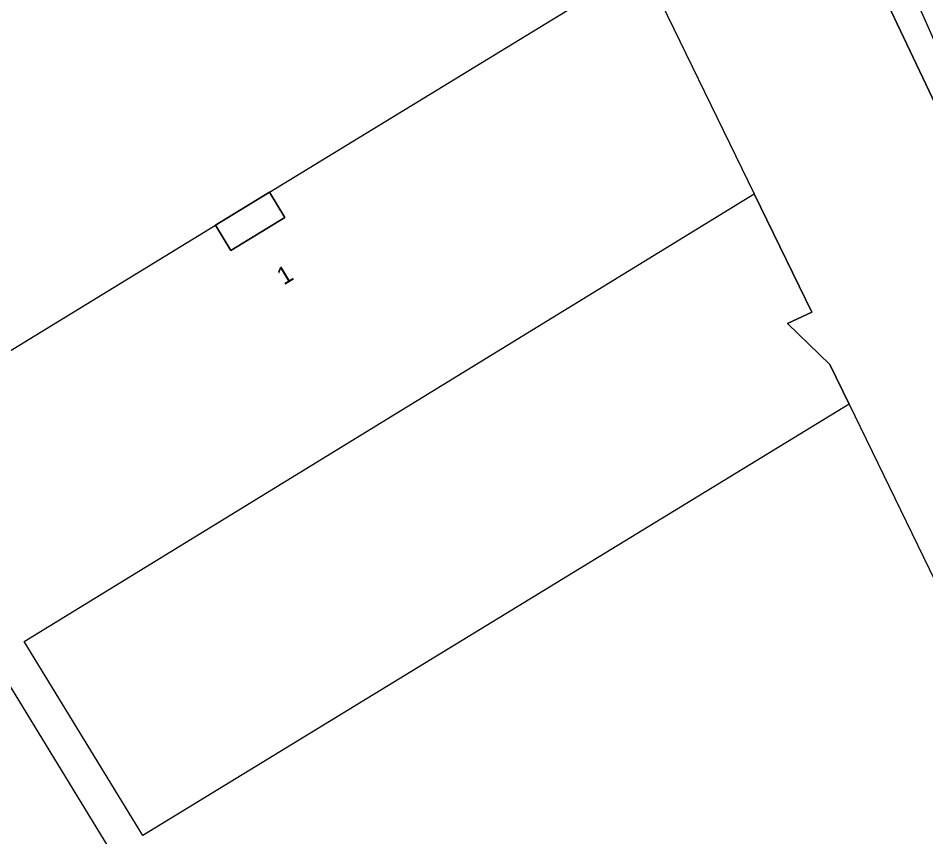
# Model space of a CAD drawing. Extents: x 158838 to 160074, y 386376 to 387776.
# Drawn here: x 159071.9 to 159123.5, y 387277.8 to 387324.4 of the extents above; entities that cross this region are included whole.
import ezdxf

# ---------------------------------------------------------------- set-up
doc = ezdxf.new("R2010")
doc.units = 0
for name, color, linetype in [('IMGEO_Hek', 7, 'Continuous'), ('IMGEO_Muur', 7, 'Continuous'), ('IMGEO_Pand', 7, 'Continuous'), ('IMGEO_Pand_nummerreeks', 7, 'Continuous'), ('IMGEO_Pand_overbouw', 7, 'Continuous'), ('IMGEO_Parkeervlak_open', 7, 'Continuous'), ('IMGEO_Voetpad_open', 7, 'Continuous')]:
    doc.layers.add(name, color=color, linetype=linetype)

msp = doc.modelspace()

# ---------------------------------------------------------------- linework, layer by layer
at = {"layer": 'IMGEO_Hek'}
msp.add_lwpolyline([(159111.223, 387350.914), (159120.947, 387325.983), (159132.639, 387301.404), (159144.696, 387277.152), (159141.337, 387268.603), (159136.701, 387264.574), (159101.97, 387242.767)], dxfattribs=at)
at = {"layer": 'IMGEO_Muur'}
msp.add_lwpolyline([(159119.127, 387302.434), (159118.037, 387304.677), (159115.624, 387307.015), (159117.002, 387307.662), (159113.737, 387314.386)], dxfattribs=at)
at = {"layer": 'IMGEO_Pand'}
for points in [[(159086.152, 387314.485), (159107.384, 387327.45), (159113.737, 387314.386)], [(159119.127, 387302.434), (159078.959, 387277.913), (159072.213, 387288.938), (159113.737, 387314.386)], [(159086.152, 387314.485), (159087.038, 387313.034), (159083.966, 387311.158), (159083.08, 387312.609)], [(159119.127, 387302.434), (159131.157, 387277.704), (159091.538, 387253.454), (159070.581, 387287.744), (159058.345, 387280.343), (159050.694, 387292.811), (159083.08, 387312.609)]]:
    msp.add_lwpolyline(points, dxfattribs=at)
at = {"layer": 'IMGEO_Pand_overbouw'}
msp.add_lwpolyline([(159083.08, 387312.609), (159083.966, 387311.158), (159087.038, 387313.034), (159086.152, 387314.485)], close=True, dxfattribs=at)
at = {"layer": 'IMGEO_Parkeervlak_open'}
for points in [[(159134.852, 387263.413), (159136.701, 387264.574), (159141.337, 387268.603), (159144.696, 387277.152), (159132.639, 387301.404), (159120.947, 387325.983), (159111.223, 387350.914)], [(159113.737, 387314.386), (159117.002, 387307.662), (159115.624, 387307.015), (159118.037, 387304.677), (159119.127, 387302.434)]]:
    msp.add_lwpolyline(points, dxfattribs=at)
at = {"layer": 'IMGEO_Voetpad_open'}
msp.add_lwpolyline([(159083.08, 387312.609), (159086.152, 387314.485)], dxfattribs=at)
msp.add_arc((160017.567, 387716.767), 976.48, 203.570188, 206.390425, dxfattribs=at)

# ---------------------------------------------------------------- texts
at = {"layer": 'IMGEO_Pand_nummerreeks'}
msp.add_text('1', height=1, rotation=30.9732, dxfattribs=at).set_placement((159086.967, 387309.169))

doc.saveas('drawing.dxf')
